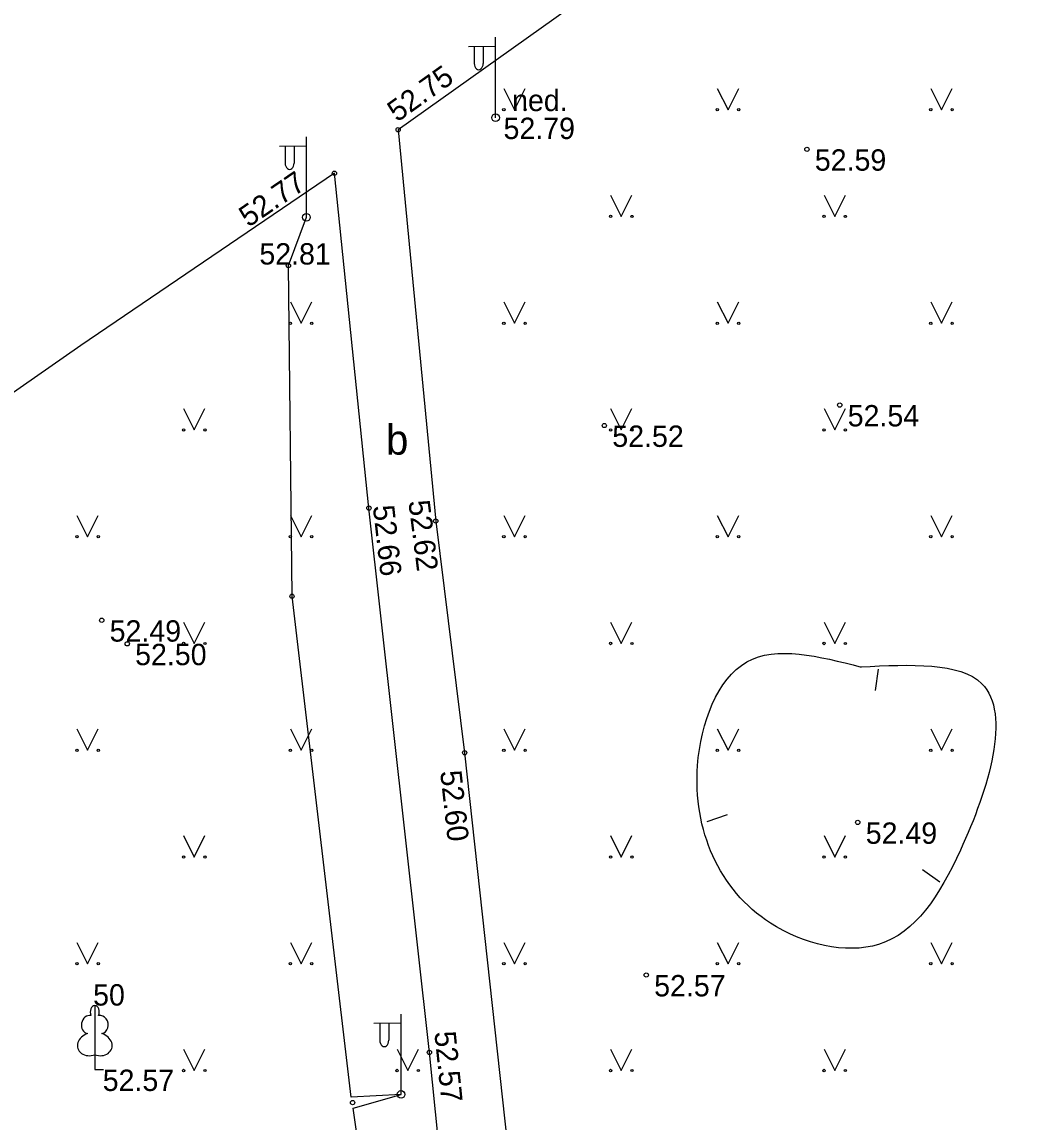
# Model space of a CAD drawing. Extents: x 619806 to 620082, y 405176 to 405386.
# Drawn here: x 619968.46 to 619991.93, y 405241.29 to 405267.05 of the extents above; entities that cross this region are included whole.
import ezdxf

# ---------------------------------------------------------------- set-up
doc = ezdxf.new("R2010")
doc.units = 0
for name, color, linetype in [('APGS_ELEM_####_####_#', 7, 'Continuous'), ('APGS_ELEM_####_TKST_#', 7, 'Continuous'), ('APGS_VADP_ZSPR_####_#', 7, 'Continuous'), ('CELI_CMAL_####_####_#', 7, 'Continuous'), ('CELI_CSEG_####_TKST_#', 7, 'Continuous'), ('RELJ_AATZ_####_TKST_#', 7, 'Continuous'), ('RELJ_ELEM_####_####_#', 7, 'Continuous'), ('RELJ_HORZ_PAMT_####_#', 7, 'Continuous'), ('TERT_DIAM_####_TKST_#', 7, 'Continuous'), ('TERT_ELEM_####_####_#', 7, 'Continuous')]:
    doc.layers.add(name, color=color, linetype=linetype)

msp = doc.modelspace()

# ---------------------------------------------------------------- linework, layer by layer
at = {"layer": 'APGS_ELEM_####_####_#'}
for p, q in [((619979.557, 405264.813), (619979.557, 405266.696)), ((619979.557, 405266.48), (619978.922, 405266.475)), ((619979.057, 405266.476), (619979.057, 405266.084)), ((619979.267, 405266.478), (619979.267, 405266.084)), ((619975.127, 405262.48), (619975.127, 405264.363)), ((619975.127, 405264.147), (619974.492, 405264.142)), ((619974.627, 405264.143), (619974.627, 405263.751)), ((619974.837, 405264.145), (619974.837, 405263.751)), ((619977.344, 405243.607), (619976.709, 405243.602)), ((619976.844, 405243.603), (619976.844, 405243.211)), ((619977.054, 405243.605), (619977.054, 405243.211)), ((619977.344, 405241.94), (619977.344, 405243.823))]:
    msp.add_line(p, q, dxfattribs=at)
for centre in [(619979.557, 405264.813), (619975.127, 405262.48), (619977.344, 405241.94)]:
    msp.add_circle(centre, 0.09, dxfattribs=at)
for centre in [(619979.162, 405266.084), (619974.732, 405263.751), (619976.949, 405243.211)]:
    msp.add_ellipse(centre, major_axis=(0, 0.151), ratio=0.695971, start_param=1.570796, end_param=4.712389, dxfattribs=at)
at = {"layer": 'APGS_VADP_ZSPR_####_#'}
msp.add_lwpolyline([(619938.618, 405223.547), (619972.929, 405204.127), (619985.155, 405202.826), (619985.811, 405203.238), (619985.154, 405203.005), (619983.308, 405203.577), (619978.291, 405211.172), (619979.175, 405220.104), (619979.035, 405222.014), (619979.51, 405222.264), (619979.008, 405222.268), (619977.44, 405233.124), (619976.223, 405241.622), (619977.344, 405241.94), (619976.176, 405241.874), (619974.789, 405253.607), (619974.705, 405261.349), (619975.127, 405262.48)], dxfattribs=at)
at = {"layer": 'CELI_CMAL_####_####_#'}
for points in [[(620044.255, 405272.554), (620043.092, 405273.429), (620033.269, 405279.026), (620025.28, 405283.562), (620015.248, 405289.312), (620013.524, 405289.938), (620004.396, 405283.537), (619995.598, 405277.461), (619983.971, 405269.299), (619977.275, 405264.531), (619978.155, 405255.368), (619978.832, 405249.941), (619981.369, 405226.774)], [(619982.283, 405204.018), (619982.381, 405205.526), (619981.404, 405213.543), (619980.879, 405217.395), (619980.193, 405224.262), (619979.707, 405227.554), (619978.646, 405227.479), (619978.06, 405232.469), (619979.052, 405232.579), (619978.008, 405242.924), (619976.591, 405255.672), (619975.781, 405263.512), (619969.844, 405259.482), (619963.066, 405254.752), (619955.624, 405249.587), (619947.422, 405243.791), (619942.081, 405239.98), (619941.835, 405240.299), (619936.133, 405229.455), (619943.441, 405225.387), (619954.092, 405219.528), (619965.106, 405213.442), (619974.994, 405207.99), (619982.283, 405204.018)]]:
    msp.add_lwpolyline(points, dxfattribs=at)
at = {"layer": 'RELJ_ELEM_####_####_#'}
for centre in [(619977.275, 405264.531), (619986.848, 405264.072), (619975.781, 405263.512), (619974.705, 405261.349), (619987.618, 405258.083), (619982.104, 405257.604), (619976.591, 405255.672), (619978.155, 405255.368), (619974.789, 405253.607), (619970.332, 405253.044), (619970.929, 405252.492), (619978.832, 405249.941), (619988.04, 405248.309), (619983.085, 405244.736), (619978.008, 405242.924), (619976.207, 405241.749)]:
    msp.add_circle(centre, 0.05, dxfattribs=at)
at = {"layer": 'RELJ_HORZ_PAMT_####_#'}
for p, q in [((619988.455, 405251.4), (619988.524, 405251.895)), ((619984.982, 405248.484), (619984.508, 405248.326)), ((619989.552, 405247.207), (619989.961, 405246.92))]:
    msp.add_line(p, q, dxfattribs=at)
for points in [[(619988.114, 405251.953), (619990.946, 405251.558), (619990.442, 405247.66), (619988.528, 405245.453), (619985.993, 405245.952), (619984.287, 405249.645), (619985.44, 405252.068), (619988.115, 405251.949)], [(619952.192, 405242.46), (619958.269, 405245.178), (619960.212, 405247.147), (619962.71, 405245.388), (619969.834, 405240.326), (619973.191, 405239.787), (619973.537, 405236.062), (619972.621, 405231.011), (619971.007, 405227.497), (619970.308, 405225.195), (619972.877, 405224.18), (619975.834, 405223.443), (619975.125, 405220.25), (619977.669, 405218.792), (619978.775, 405216.928), (619978.459, 405213.841), (619976.501, 405213.003), (619972.992, 405212.359), (619969.535, 405213.328), (619966.616, 405215.931), (619967.251, 405218.057), (619966.078, 405220.067), (619963.269, 405223.678), (619959.906, 405226.02), (619956.916, 405226.372), (619951.315, 405227.272), (619948.301, 405227.78), (619946.134, 405229.326), (619943.292, 405232.49), (619942.821, 405234.331), (619944.296, 405235.783), (619946.209, 405238.021), (619948.046, 405239.888), (619950.691, 405241.967), (619952.192, 405242.46)]]:
    msp.add_spline(points, degree=3, dxfattribs=at)
at = {"layer": 'TERT_ELEM_####_####_#'}
for p, q in [((619979.75, 405265.5), (619980, 405265)), ((619980, 405265), (619980.25, 405265.5)), ((619984.75, 405265.5), (619985, 405265)), ((619985, 405265), (619985.25, 405265.5)), ((619989.75, 405265.5), (619990, 405265)), ((619990, 405265), (619990.25, 405265.5)), ((619982.25, 405263), (619982.5, 405262.5)), ((619982.5, 405262.5), (619982.75, 405263)), ((619987.25, 405263), (619987.5, 405262.5)), ((619987.5, 405262.5), (619987.75, 405263)), ((619974.75, 405260.5), (619975, 405260)), ((619975, 405260), (619975.25, 405260.5)), ((619979.75, 405260.5), (619980, 405260)), ((619980, 405260), (619980.25, 405260.5)), ((619984.75, 405260.5), (619985, 405260)), ((619985, 405260), (619985.25, 405260.5)), ((619989.75, 405260.5), (619990, 405260)), ((619990, 405260), (619990.25, 405260.5)), ((619972.25, 405258), (619972.5, 405257.5)), ((619972.5, 405257.5), (619972.75, 405258)), ((619982.25, 405258), (619982.5, 405257.5)), ((619982.5, 405257.5), (619982.75, 405258)), ((619987.25, 405258), (619987.5, 405257.5)), ((619987.5, 405257.5), (619987.75, 405258)), ((619969.75, 405255.5), (619970, 405255)), ((619970, 405255), (619970.25, 405255.5)), ((619974.75, 405255.5), (619975, 405255)), ((619975, 405255), (619975.25, 405255.5)), ((619979.75, 405255.5), (619980, 405255)), ((619980, 405255), (619980.25, 405255.5)), ((619984.75, 405255.5), (619985, 405255)), ((619985, 405255), (619985.25, 405255.5)), ((619989.75, 405255.5), (619990, 405255)), ((619990, 405255), (619990.25, 405255.5)), ((619972.25, 405253), (619972.5, 405252.5)), ((619972.5, 405252.5), (619972.75, 405253)), ((619982.25, 405253), (619982.5, 405252.5)), ((619982.5, 405252.5), (619982.75, 405253)), ((619987.25, 405253), (619987.5, 405252.5)), ((619987.5, 405252.5), (619987.75, 405253)), ((619969.75, 405250.5), (619970, 405250)), ((619970, 405250), (619970.25, 405250.5)), ((619974.75, 405250.5), (619975, 405250)), ((619975, 405250), (619975.25, 405250.5)), ((619979.75, 405250.5), (619980, 405250)), ((619980, 405250), (619980.25, 405250.5)), ((619984.75, 405250.5), (619985, 405250)), ((619985, 405250), (619985.25, 405250.5)), ((619989.75, 405250.5), (619990, 405250)), ((619990, 405250), (619990.25, 405250.5)), ((619972.25, 405248), (619972.5, 405247.5)), ((619972.5, 405247.5), (619972.75, 405248)), ((619982.25, 405248), (619982.5, 405247.5)), ((619982.5, 405247.5), (619982.75, 405248)), ((619987.25, 405248), (619987.5, 405247.5)), ((619987.5, 405247.5), (619987.75, 405248)), ((619969.75, 405245.5), (619970, 405245)), ((619970, 405245), (619970.25, 405245.5)), ((619974.75, 405245.5), (619975, 405245)), ((619975, 405245), (619975.25, 405245.5)), ((619979.75, 405245.5), (619980, 405245)), ((619980, 405245), (619980.25, 405245.5)), ((619984.75, 405245.5), (619985, 405245)), ((619985, 405245), (619985.25, 405245.5)), ((619989.75, 405245.5), (619990, 405245)), ((619990, 405245), (619990.25, 405245.5)), ((619970.17, 405242.868), (619970.17, 405242.521)), ((619972.25, 405243), (619972.5, 405242.5)), ((619972.5, 405242.5), (619972.75, 405243)), ((619977.25, 405243), (619977.5, 405242.5)), ((619977.5, 405242.5), (619977.75, 405243)), ((619982.25, 405243), (619982.5, 405242.5)), ((619982.5, 405242.5), (619982.75, 405243)), ((619987.25, 405243), (619987.5, 405242.5)), ((619987.5, 405242.5), (619987.75, 405243)), ((619970.17, 405242.521), (619970.37, 405242.521))]:
    msp.add_line(p, q, dxfattribs=at)
for points in [[(619970.17, 405244.021), (619970.17, 405242.868)], [(619970.26, 405243.789), (619970.259, 405243.79)]]:
    msp.add_lwpolyline(points, dxfattribs=at)
for centre, radius in [((619979.75, 405265), 0.028), ((619980.25, 405265), 0.0263), ((619984.75, 405265), 0.028), ((619985.25, 405265), 0.0263), ((619989.75, 405265), 0.028), ((619990.25, 405265), 0.0263), ((619982.25, 405262.5), 0.028), ((619982.75, 405262.5), 0.0263), ((619987.25, 405262.5), 0.028), ((619987.75, 405262.5), 0.0263), ((619974.75, 405260), 0.028), ((619975.25, 405260), 0.0263), ((619979.75, 405260), 0.028), ((619980.25, 405260), 0.0263), ((619984.75, 405260), 0.028), ((619985.25, 405260), 0.0263), ((619989.75, 405260), 0.028), ((619990.25, 405260), 0.0263), ((619972.25, 405257.5), 0.028), ((619972.75, 405257.5), 0.0263), ((619982.25, 405257.5), 0.028), ((619982.75, 405257.5), 0.0263), ((619987.25, 405257.5), 0.028), ((619987.75, 405257.5), 0.0263), ((619969.75, 405255), 0.028), ((619970.25, 405255), 0.0263), ((619974.75, 405255), 0.028), ((619975.25, 405255), 0.0263), ((619979.75, 405255), 0.028), ((619980.25, 405255), 0.0263), ((619984.75, 405255), 0.028), ((619985.25, 405255), 0.0263), ((619989.75, 405255), 0.028), ((619990.25, 405255), 0.0263), ((619972.25, 405252.5), 0.028), ((619972.75, 405252.5), 0.0263), ((619982.25, 405252.5), 0.028), ((619982.75, 405252.5), 0.0263), ((619987.25, 405252.5), 0.028), ((619987.75, 405252.5), 0.0263), ((619969.75, 405250), 0.028), ((619970.25, 405250), 0.0263), ((619974.75, 405250), 0.028), ((619975.25, 405250), 0.0263), ((619979.75, 405250), 0.028), ((619980.25, 405250), 0.0263), ((619984.75, 405250), 0.028), ((619985.25, 405250), 0.0263), ((619989.75, 405250), 0.028), ((619990.25, 405250), 0.0263), ((619972.25, 405247.5), 0.028), ((619972.75, 405247.5), 0.0263), ((619982.25, 405247.5), 0.028), ((619982.75, 405247.5), 0.0263), ((619987.25, 405247.5), 0.028), ((619987.75, 405247.5), 0.0263), ((619969.75, 405245), 0.028), ((619970.25, 405245), 0.0263), ((619974.75, 405245), 0.028), ((619975.25, 405245), 0.0263), ((619979.75, 405245), 0.028), ((619980.25, 405245), 0.0263), ((619984.75, 405245), 0.028), ((619985.25, 405245), 0.0263), ((619989.75, 405245), 0.028), ((619990.25, 405245), 0.0263), ((619972.25, 405242.5), 0.028), ((619972.75, 405242.5), 0.0263), ((619977.25, 405242.5), 0.028), ((619977.75, 405242.5), 0.0263), ((619982.25, 405242.5), 0.028), ((619982.75, 405242.5), 0.0263), ((619987.25, 405242.5), 0.028), ((619987.75, 405242.5), 0.0263)]:
    msp.add_circle(centre, radius, dxfattribs=at)
for centre, major_axis, ratio, start_param, end_param in [((619970.17, 405243.871), (0, -0.15), 0.707107, 3.14537, 5.287485), ((619970.17, 405243.871), (0, -0.15), 0.707107, 0.995701, 3.137816), ((619970.042, 405243.576), (-0.039, -0.212), 0.861323, 3.141593, 6.283185), ((619970.298, 405243.576), (0.039, -0.212), 0.861323, 0, 3.141593), ((619970.08, 405243.114), (0.307, 0.095), 0.814445, 1.570796, 4.752015), ((619970.26, 405243.114), (-0.307, 0.095), 0.814445, 1.531171, 4.712389)]:
    msp.add_ellipse(centre, major_axis=major_axis, ratio=ratio, start_param=start_param, end_param=end_param, dxfattribs=at)

# ---------------------------------------------------------------- texts
at = {"layer": 'APGS_ELEM_####_TKST_#'}
msp.add_text('ned.', height=0.5, dxfattribs=at).set_placement((619979.943, 405264.968))
at = {"layer": 'CELI_CSEG_####_TKST_#'}
msp.add_text('b', height=0.7, dxfattribs=at).set_placement((619976.992, 405256.923))
at = {"layer": 'RELJ_AATZ_####_TKST_#'}
for s, rotation, p in [(' 52.75', 35.4534, (619977.101, 405264.588)), (' 52.77', 34.2964, (619973.615, 405262.128)), (' 52.66', 276.3256, (619976.661, 405255.901)), (' 52.62', 277.1107, (619977.49, 405256.014)), (' 52.60', 276.2495, (619978.237, 405249.689)), (' 52.57', 275.7627, (619978.103, 405243.583))]:
    msp.add_text(s, height=0.5, rotation=rotation, dxfattribs=at).set_placement(p)
for s, p in [(' 52.79', (619979.557, 405264.313)), (' 52.59', (619986.848, 405263.572)), (' 52.81', (619973.839, 405261.374)), (' 52.54', (619987.618, 405257.583)), (' 52.52', (619982.104, 405257.104)), (' 52.49', (619970.332, 405252.544)), (' 52.50', (619970.929, 405251.992)), (' 52.49', (619988.04, 405247.809)), (' 52.57', (619983.085, 405244.236)), (' 52.57', (619970.17, 405242.021))]:
    msp.add_text(s, height=0.5, dxfattribs=at).set_placement(p)
at = {"layer": 'TERT_DIAM_####_TKST_#'}
msp.add_text(' 50', height=0.5, dxfattribs=at).set_placement((619969.945, 405244.021))

doc.saveas('drawing.dxf')
